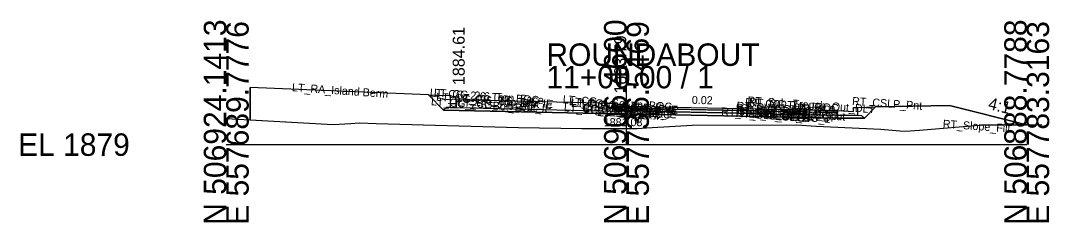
# Model space of a CAD drawing. Extents: x -36 to 140, y -10 to 2515.
# Drawn here: x -35.7 to 92.8, y 990.3 to 1015.5 of the extents above; entities that cross this region are included whole.
import ezdxf

# ---------------------------------------------------------------- set-up
doc = ezdxf.new("R2010")
doc.units = 0
for name, color, linetype in [('Default', 7, 'Continuous'), ('Exist Cross Section Cell', 7, 'Continuous'), ('Exist XS Center Line Elevation Label', 7, 'Continuous'), ('Exist XS Ground Line', 7, 'Continuous'), ('Prop CMT Conc Surface', 7, 'Continuous'), ('Prop CMT Concrete Structures', 7, 'Continuous'), ('Prop CMT Pvmt Course 1', 7, 'Continuous'), ('Prop CMT Pvmt Course 1 CG', 7, 'Continuous'), ('Prop CMT Pvmt Course 2', 7, 'Continuous'), ('Prop CMT Pvmt Course 3', 7, 'Continuous'), ('Prop CMT Pvmt Course 4', 7, 'Continuous'), ('Prop CMT Slope Grass', 7, 'Continuous'), ('Prop CMT Subgrade Earthwork', 7, 'Continuous'), ('Prop Conc 4in Sidewalk', 7, 'Continuous'), ('Prop Conc Curb and Gutter', 7, 'Continuous'), ('Prop XS Earthwork Shape', 7, 'Continuous'), ('Prop XS Finish Grade Earthwork', 7, 'Continuous'), ('Prop XS Hydro Elevations', 7, 'Continuous'), ('Prop XS Side Slope Text', 7, 'Continuous'), ('Typical Structure Recommendation Sheet 1 CELL', 7, 'Continuous')]:
    doc.layers.add(name, color=color, linetype=linetype)

msp = doc.modelspace()

# ---------------------------------------------------------------- linework, layer by layer
at = {"layer": 'Exist Cross Section Cell'}
for p, q in [((40, 1000), (40, 1009.82)), ((-10, 1000), (40, 1000)), ((40, 1000), (90, 1000))]:
    msp.add_line(p, q, dxfattribs=at)
at = {"layer": 'Exist XS Ground Line'}
msp.add_lwpolyline([(-10, 1003.27), (3.35, 1002.53), (5.56, 1002.65), (6.59, 1002.71), (8.73, 1002.64), (26.51, 1002.15), (34.41, 1002.02), (40, 1002.03), (40.44, 1002.03), (41.34, 1002.02), (42.49, 1002.09), (46.07, 1002.3), (48.19, 1002.42), (61.24, 1002.46), (63.68, 1002.32), (71.77, 1001.91), (74.14, 1001.74), (74.86, 1001.7), (76.6, 1001.8), (84.55, 1002.47), (86.78, 1002.45), (91.89, 1002.49)], dxfattribs=at)
at = {"layer": 'Prop CMT Conc Surface'}
for p, q in [((18.62, 1005.89), (17.97, 1006.11)), ((17.97, 1006.11), (17.97, 1005.11)), ((18.72, 1005.11), (18.72, 1005.75)), ((38.47, 1004.19), (38.47, 1005.19)), ((39.15, 1004.97), (38.47, 1005.19)), ((17.16, 1004.3), (17.47, 1004.61)), ((17.97, 1004.61), (17.47, 1004.61)), ((17.97, 1005.11), (18.72, 1005.11)), ((17.97, 1005.11), (17.97, 1004.61)), ((17.97, 1004.61), (18.72, 1004.61)), ((18.72, 1004.61), (18.72, 1005.11)), ((39.97, 1004.19), (38.47, 1004.19)), ((38.55, 1004.4), (38.48, 1004.39)), ((38.48, 1004.39), (38.52, 1004.28)), ((38.52, 1004.28), (38.55, 1004.4)), ((38.61, 1005.02), (38.53, 1005.02)), ((38.53, 1005.02), (38.61, 1004.94)), ((38.61, 1004.94), (38.61, 1005.02)), ((38.81, 1004.72), (38.85, 1004.57)), ((38.89, 1004.66), (38.81, 1004.72)), ((38.85, 1004.57), (38.89, 1004.66)), ((39.12, 1004.43), (39.21, 1004.38)), ((39.15, 1004.3), (39.12, 1004.43)), ((39.21, 1004.38), (39.15, 1004.3)), ((39.22, 1004.87), (39.22, 1004.88)), ((39.97, 1004.78), (39.31, 1004.78)), ((39.47, 1004.39), (39.4, 1004.37)), ((39.4, 1004.37), (39.44, 1004.27)), ((39.44, 1004.27), (39.47, 1004.39)), ((39.73, 1004.7), (39.77, 1004.56)), ((39.81, 1004.65), (39.73, 1004.7)), ((39.77, 1004.56), (39.81, 1004.65)), ((39.97, 1004.78), (39.97, 1004.19)), ((39.97, 1004.19), (39.97, 1004.77))]:
    msp.add_line(p, q, dxfattribs=at)
msp.add_lwpolyline([(39.97, 1004.2), (39.97, 1004.78)], dxfattribs=at)
msp.add_lwpolyline([(39.97, 1004.2), (39.97, 1004.78)], dxfattribs=at)
for centre in [(38.54, 1004.78), (38.55, 1004.67), (38.59, 1004.3), (38.61, 1004.52), (38.68, 1005.11), (38.7, 1004.66), (38.7, 1004.82), (38.73, 1004.26), (38.74, 1004.53), (38.76, 1004.43), (38.82, 1004.77), (38.89, 1004.92), (38.89, 1004.5), (38.99, 1004.64), (38.99, 1004.25), (39.01, 1004.78), (39.01, 1004.37), (39.03, 1004.94), (39.04, 1004.5), (39.08, 1004.69), (39.2, 1004.72), (39.22, 1004.62), (39.24, 1004.24), (39.31, 1004.38), (39.31, 1004.23), (39.33, 1004.46), (39.34, 1004.69), (39.35, 1004.66), (39.47, 1004.66), (39.51, 1004.29), (39.53, 1004.5), (39.62, 1004.65), (39.65, 1004.25), (39.66, 1004.51), (39.68, 1004.42), (39.74, 1004.76), (39.81, 1004.48), (39.91, 1004.63), (39.91, 1004.23), (39.93, 1004.35), (39.96, 1004.49)]:
    msp.add_circle(centre, 0.00635, dxfattribs=at)
for centre, radius, start, end in [((18.57, 1005.75), 0.146, 0, 71.5651), ((38.5, 1004.2), 0.00635, 27.0386, 154.2416), ((39.12, 1004.88), 0.0937, 0, 71.5651), ((39.31, 1004.87), 0.0937, 180, 270)]:
    msp.add_arc(centre, radius, start, end, dxfattribs=at)
at = {"layer": 'Prop CMT Concrete Structures'}
msp.add_lwpolyline([(66.36, 1004.26), (68.36, 1004.15), (68.36, 1004.65), (68.86, 1004.65)], dxfattribs=at)
at = {"layer": 'Prop CMT Pvmt Course 1'}
for points in [[(39.97, 1004.53), (39.97, 1004.78)], [(39.97, 1004.78), (66.36, 1004.26)], [(39.97, 1004.53), (39.97, 1004.78)], [(39.97, 1004.53), (39.97, 1004.78)], [(57.97, 1004.17), (39.97, 1004.53)], [(66.36, 1004.26), (66.36, 1004.01)], [(66.36, 1004.26), (66.36, 1004.01)]]:
    msp.add_lwpolyline(points, dxfattribs=at)
at = {"layer": 'Prop CMT Pvmt Course 1 CG'}
msp.add_lwpolyline([(66.36, 1003.42), (66.36, 1003.67)], dxfattribs=at)
at = {"layer": 'Prop CMT Pvmt Course 2'}
for points in [[(39.97, 1004.19), (39.97, 1004.53)], [(39.97, 1004.2), (39.97, 1004.53)], [(39.97, 1004.53), (66.36, 1004.01)], [(39.97, 1004.2), (39.97, 1004.53)], [(57.97, 1003.84), (39.97, 1004.2)], [(66.36, 1003.86), (66.36, 1003.53)]]:
    msp.add_lwpolyline(points, dxfattribs=at)
at = {"layer": 'Prop CMT Pvmt Course 3'}
for points in [[(39.97, 1004.2), (66.36, 1003.67)], [(66.36, 1003.67), (66.36, 1003.32)], [(66.36, 1003.67), (66.36, 1003.34)]]:
    msp.add_lwpolyline(points, dxfattribs=at)
at = {"layer": 'Prop CMT Pvmt Course 4'}
for points in [[(39.97, 1003.87), (39.97, 1003.87)], [(39.97, 1003.87), (39.97, 1003.87)], [(39.97, 1003.86), (39.97, 1003.86)], [(66.36, 1003.34), (66.36, 1003.34)], [(66.36, 1003.34), (66.36, 1003.34)]]:
    msp.add_lwpolyline(points, dxfattribs=at)
at = {"layer": 'Prop CMT Slope Grass'}
msp.add_line((-7.03, 1003.11), (-7.03, 1007.11), dxfattribs=at)
for points in [[(15.26, 1006.21), (-7.03, 1007.11)], [(71.1, 1004.7), (80.36, 1004.88), (89.97, 1002.48)]]:
    msp.add_lwpolyline(points, dxfattribs=at)
at = {"layer": 'Prop CMT Subgrade Earthwork'}
for p, q in [((17.16, 1004.3), (15.26, 1006.21)), ((17.16, 1004.3), (38.46, 1003.86)), ((38.46, 1003.86), (39.95, 1003.86)), ((39.95, 1003.86), (66.36, 1003.31)), ((69.72, 1003.28), (71.1, 1004.7))]:
    msp.add_line(p, q, dxfattribs=at)
msp.add_lwpolyline([(66.36, 1003.32), (69.72, 1003.28)], dxfattribs=at)
at = {"layer": 'Prop Conc 4in Sidewalk'}
for p, q in [((18.72, 1005.61), (18.72, 1004.61)), ((18.72, 1005.61), (38.47, 1005.19)), ((18.72, 1004.61), (38.47, 1004.19))]:
    msp.add_line(p, q, dxfattribs=at)
at = {"layer": 'Prop Conc Curb and Gutter'}
for points in [[(66.36, 1004.26), (68.36, 1004.15), (68.36, 1004.65), (68.86, 1004.65)], [(68.86, 1004.65), (68.86, 1003.64), (66.36, 1003.67)], [(66.36, 1003.67), (66.36, 1004.26)], [(66.36, 1003.67), (69.36, 1003.64), (69.72, 1003.28)]]:
    msp.add_lwpolyline(points, dxfattribs=at)
at = {"layer": 'Prop XS Earthwork Shape'}
msp.add_lwpolyline([(74.86, 1001.7), (76.6, 1001.8), (84.55, 1002.47), (86.78, 1002.45), (89.97, 1002.48), (80.36, 1004.88), (71.1, 1004.7), (69.72, 1003.28), (66.36, 1003.31), (39.95, 1003.86), (38.46, 1003.86), (17.16, 1004.3), (15.26, 1006.21), (-7.03, 1007.11), (-7.03, 1003.11), (3.35, 1002.53), (5.56, 1002.65), (6.59, 1002.71), (8.73, 1002.64), (26.51, 1002.15), (34.41, 1002.02), (40, 1002.03), (40.44, 1002.03), (41.34, 1002.02), (42.49, 1002.09), (46.07, 1002.3), (48.19, 1002.42), (61.24, 1002.46), (63.68, 1002.32), (71.77, 1001.91), (74.14, 1001.74)], close=True, dxfattribs=at)
at = {"layer": 'Prop XS Finish Grade Earthwork'}
for p, q in [((15.26, 1006.21), (17.97, 1006.11)), ((68.86, 1004.65), (71.1, 1004.7))]:
    msp.add_line(p, q, dxfattribs=at)

# ---------------------------------------------------------------- texts
at = {"layer": 'Default'}
for p in [(-0.03, 1003.44), (0, 1000)]:
    msp.add_text('-', height=0.0001, dxfattribs=at).set_placement(p)
at = {"layer": 'Exist Cross Section Cell'}
for s, p in [('N 506924.1413', (-10, 990)), ('N 506906.4600', (40, 990)), ('N 506888.7788', (90, 990)), ('E 557689.7776', (-7.2, 990)), ('E 557736.5469', (42.8, 990)), ('E 557783.3163', (92.8, 990))]:
    msp.add_text(s, height=2.8, rotation=90, dxfattribs=at).set_placement(p)
for s, p in [('ROUNDABOUT', (30, 1009.82)), ('11+00.00 / 1', (30, 1007.02)), ('EL 1879', (-36, 998.6))]:
    msp.add_text(s, height=2.8, dxfattribs=at).set_placement(p)
at = {"layer": 'Exist XS Center Line Elevation Label'}
msp.add_text('1881.03', height=1, dxfattribs=at).set_placement((37.16, 1002.3))
at = {"layer": 'Prop XS Hydro Elevations'}
for s, height, rotation, p in [('1884.61', 1.5, 90, (19.79, 1007.42)), ('1883.79', 1.5, 90, (39.97, 1006.37)), ('0.02', 1, 358.8542, (48.16, 1005.08))]:
    msp.add_text(s, height=height, rotation=rotation, dxfattribs=at).set_placement(p)
at = {"layer": 'Prop XS Side Slope Text'}
msp.add_text('4:1', height=1.5, rotation=345.9548, dxfattribs=at).set_placement((85.08, 1004.47))
at = {"layer": 'Typical Structure Recommendation Sheet 1 CELL'}
for s, p in [('LT_RA_Island Berm', (-1.81, 1006.67)), ('LT_CG_2-6_Top_BOC', (15.41, 1006)), ('LT_CG_2-6_Top_Face', (15.92, 1006)), ('LT_CG_2-6_Top_Gut', (16.19, 1005.48)), ('LT_CG_2-6_Bot_BOC', (15.55, 1004.92)), ('LT_CG_2-6_Top_IE', (18.78, 1005.4)), ('LT_CG_2-6_Bot_IE', (18.92, 1004.8)), ('LT_CG_1-6_Top_BOC', (32.02, 1005.16)), ('LT_CG_1-6_Bot_BOC', (32.16, 1004.16)), ('LT_CG_1-6_Top_Face', (32.79, 1004.91)), ('LT_CG_1-6_Top_Gut', (33.06, 1004.72)), ('LT_CG_1-6_Top_IE', (34.4, 1004.67)), ('LT_MI_BOC', (35.01, 1004.37)), ('LT_PV2_PGL', (36.32, 1004.29)), ('RT_PV1_OEOT', (53.73, 1004.36)), ('RT_CG_Top_Face', (54.79, 1004.82)), ('RT_CG_Top_Gut', (55.05, 1004.3)), ('RT_Sub_Trench_Out_DLT', (55.09, 1005.02)), ('RT_CG_Top_BOC', (55.28, 1004.82)), ('RT_CSLP_Pnt', (68.16, 1004.95)), ('LT_CG_1-6_Bot_IE', (34.54, 1004.08)), ('LT_PV3_PGL', (36.32, 1003.95)), ('LT_PV4_PGL', (36.32, 1003.62)), ('LT_Sub_PGL', (36.35, 1003.62)), ('RT_Sub_OEOT_CG_1', (51.81, 1003.66)), ('RT_PV2_OEOT', (53.62, 1004.12)), ('RT_PV3_OEOT', (53.62, 1003.78)), ('RT_PV4_OEOT', (53.62, 1003.45)), ('RT_Sub_OEOT', (53.64, 1003.45)), ('RT_CG_Bot_IE', (53.79, 1003.77)), ('RT_CG1_Shelf_Out', (55.36, 1003.83)), ('RT_CG_Bot_BOC', (55.41, 1003.8)), ('RT_Sub_OEOP', (56.89, 1003.49)), ('RT_Slope_Fill', (79.49, 1002.11))]:
    msp.add_text(s, height=1, rotation=356, dxfattribs=at).set_placement(p)

doc.saveas('drawing.dxf')
